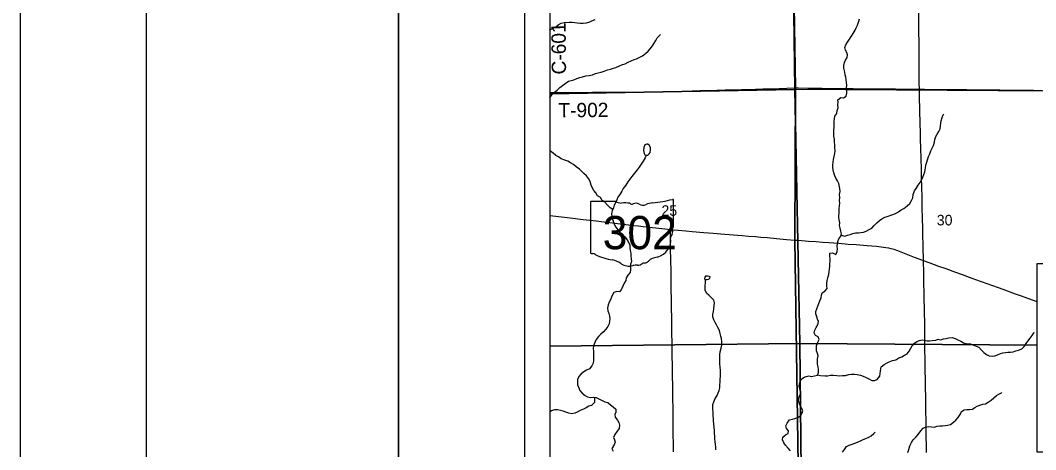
# Model space of a CAD drawing. Extents: x 0 to 34, y 0 to 22.
# Drawn here: x 0 to 4.028, y 17.462 to 19.165 of the extents above; entities that cross this region are included whole.
import ezdxf

# ---------------------------------------------------------------- set-up
doc = ezdxf.new("R2010")
doc.units = 0
for name, color, linetype in [('Default', 7, 'Continuous'), ('GM_X_County_Road_Text', 7, 'Continuous'), ('GM_X_Interstate_Route', 7, 'Continuous'), ('GM_X_Minor_Lake', 7, 'Continuous'), ('GM_X_Minor_River', 7, 'Continuous'), ('GM_X_Section', 7, 'Continuous'), ('GM_X_Section_Text', 7, 'Continuous'), ('GM_X_State_Location', 7, 'Continuous'), ('GM_X_State_Route', 7, 'Continuous'), ('GM_X_State_Shield', 7, 'Continuous'), ('GM_X_Township_Road', 7, 'Continuous'), ('GM_X_Township_Road_Text', 7, 'Continuous'), ('SH_Border', 7, 'Continuous'), ('SH_Cut_Line', 7, 'Continuous'), ('SH_Data', 7, 'Continuous')]:
    doc.layers.add(name, color=color, linetype=linetype)

msp = doc.modelspace()

# ---------------------------------------------------------------- linework, layer by layer
at = {"layer": 'Default'}
for points in [[(2.1, 19.8813), (2.1, 18.8733), (3.073, 18.8909), (3.0592, 19.8987), (3.0228, 19.9046), (2.4888, 19.8857)], [(2.1, 18.8733), (2.1, 17.8727), (3.0924, 17.8824), (3.073, 18.8909)], [(2.1, 17.8727), (2.1, 16.8795), (2.253, 16.8782), (3.1023, 16.8785), (3.0924, 17.8824)]]:
    msp.add_lwpolyline(points, close=True, dxfattribs=at)
at = {"layer": 'GM_X_Interstate_Route'}
msp.add_lwpolyline([(3.0331, 20.9), (2.1, 20.9), (2.1, 16.8784), (2.6014, 16.878), (3.0939, 16.8719), (3.0724, 18.2926), (3.0747, 18.8969), (3.067, 19.3838), (3.0588, 19.9042)], close=True, dxfattribs=at)
msp.add_lwpolyline([(8.1285, 16.8707), (8.1148, 17.8694), (8.0976, 18.2853), (8.0958, 18.3144), (8.0817, 18.88), (8.0959, 19.2713), (8.1023, 19.3817), (8.0929, 19.6339), (8.0678, 20.8562), (8.0675, 20.8733), (8.067, 20.8954), (8.0669, 20.9), (3.0331, 20.9), (3.0588, 19.9042), (3.067, 19.3838), (3.0747, 18.8969), (3.0724, 18.2926), (3.0939, 16.8719)], dxfattribs=at)
at = {"layer": 'GM_X_Minor_Lake'}
for points in [[(2.4888, 18.6297), (2.4941, 18.6349), (2.4983, 18.6402), (2.5003, 18.6516), (2.5004, 18.6588), (2.4955, 18.6676), (2.4899, 18.6737), (2.485, 18.6737), (2.477, 18.6704), (2.4735, 18.6606), (2.4719, 18.6481), (2.4744, 18.637)], [(2.4744, 18.637), (2.4772, 18.6309), (2.4801, 18.6297), (2.4821, 18.6293), (2.4839, 18.6294), (2.4888, 18.6297)], [(2.7247, 18.1372), (2.73, 18.1383), (2.7326, 18.1401), (2.7357, 18.142), (2.7369, 18.1469), (2.7323, 18.1485), (2.7267, 18.1505), (2.7183, 18.1502), (2.7149, 18.146), (2.7137, 18.14), (2.7166, 18.137)], [(2.7166, 18.137), (2.7247, 18.1372)]]:
    msp.add_lwpolyline(points, dxfattribs=at)
at = {"layer": 'GM_X_Minor_River'}
for points in [[(2.1, 19.1258), (2.1011, 19.1266), (2.1114, 19.1322), (2.1232, 19.1374), (2.1342, 19.1468), (2.1452, 19.1531), (2.1574, 19.1564), (2.1771, 19.1577), (2.1892, 19.1572), (2.1998, 19.1556), (2.2096, 19.1548), (2.2214, 19.1535), (2.2327, 19.153), (2.2456, 19.1544), (2.2589, 19.1588), (2.2703, 19.164), (2.2809, 19.1681)], [(3.2243, 18.602), (3.2255, 18.6126), (3.2279, 18.6244), (3.2306, 18.6361), (3.2319, 18.6467), (3.2316, 18.66), (3.2309, 18.671), (3.2303, 18.6809), (3.2296, 18.6934), (3.2271, 18.7059), (3.2275, 18.7162), (3.2276, 18.7298), (3.2285, 18.7397), (3.2278, 18.753), (3.2279, 18.7632), (3.2292, 18.7738), (3.2315, 18.7852), (3.2384, 18.7954), (3.2397, 18.8064), (3.2443, 18.8181), (3.2433, 18.8298), (3.2441, 18.8397), (3.2431, 18.8496), (3.2545, 18.8589), (3.2651, 18.8569), (3.2754, 18.8641), (3.2785, 18.8762), (3.279, 18.8864), (3.2779, 18.8959), (3.2784, 18.9073), (3.277, 18.9187), (3.2759, 18.9289), (3.2749, 18.9388), (3.2716, 18.9491), (3.2701, 18.9597), (3.2672, 18.9745), (3.2666, 18.9859), (3.2689, 18.9969), (3.2732, 19.0067), (3.2805, 19.0173), (3.2817, 19.0275), (3.2787, 19.037), (3.2735, 19.0469), (3.271, 19.0568), (3.2741, 19.067), (3.2814, 19.0783), (3.2967, 19.1017), (3.3044, 19.113), (3.3117, 19.1251), (3.3163, 19.1353), (3.3206, 19.1459), (3.3268, 19.161), (3.3287, 19.1708)], [(2.1, 18.8567), (2.1007, 18.8573), (2.1091, 18.8686), (2.1194, 18.8799), (2.129, 18.8881), (2.14, 18.8983), (2.1503, 18.9065), (2.1606, 18.9128), (2.1747, 18.9229), (2.1853, 18.9266), (2.196, 18.9292), (2.207, 18.9344), (2.2195, 18.9377), (2.2301, 18.9406), (2.2427, 18.9447), (2.2559, 18.9457), (2.2692, 18.9486), (2.2818, 18.9542), (2.2916, 18.956), (2.3045, 18.9596), (2.3159, 18.9633), (2.3288, 18.9681), (2.3417, 18.971), (2.3531, 18.9755), (2.3626, 18.978), (2.3763, 18.9843), (2.3892, 18.9891), (2.3987, 18.9925), (2.4116, 18.9988), (2.4234, 19.0044), (2.4345, 19.0096), (2.4447, 19.0125), (2.4576, 19.0188), (2.4679, 19.024), (2.4797, 19.0334), (2.4904, 19.042), (2.4984, 19.0522), (2.5076, 19.0639), (2.5142, 19.0744), (2.5211, 19.0846), (2.5268, 19.0948), (2.5349, 19.1046), (2.5394, 19.1079)], [(3.256, 18.3129), (3.2706, 18.3091), (3.2817, 18.3131), (3.2915, 18.3157), (3.3029, 18.3194), (3.3132, 18.3215), (3.3245, 18.3222), (3.3344, 18.3236), (3.345, 18.3243), (3.356, 18.3283), (3.3678, 18.3347), (3.3777, 18.3403), (3.3876, 18.3508), (3.3979, 18.3621), (3.4082, 18.3707), (3.4178, 18.3774), (3.4296, 18.3838), (3.4391, 18.3871), (3.4607, 18.3941), (3.4713, 18.3982), (3.4831, 18.4052), (3.4942, 18.4127), (3.5048, 18.4179), (3.5174, 18.4284), (3.5285, 18.4378), (3.5358, 18.4503), (3.5404, 18.4605), (3.5424, 18.4733), (3.5471, 18.4881), (3.5532, 18.4983), (3.562, 18.5107), (3.5697, 18.5216), (3.5759, 18.533), (3.5801, 18.5428), (3.5844, 18.5537), (3.5875, 18.5636), (3.591, 18.5802), (3.5923, 18.5901), (3.5954, 18.6022), (3.6032, 18.6249), (3.6085, 18.6355), (3.6124, 18.6468), (3.6171, 18.6581), (3.6221, 18.6687), (3.626, 18.6816), (3.6283, 18.6918), (3.6322, 18.7035), (3.6376, 18.7133), (3.6434, 18.7235), (3.6488, 18.7341), (3.6496, 18.7466), (3.6512, 18.7564), (3.6532, 18.7663), (3.6567, 18.7788), (3.6614, 18.7901), (3.6633, 18.7927)], [(2.3501, 18.4146), (2.3405, 18.4217), (2.3288, 18.4317), (2.3183, 18.4435), (2.3085, 18.4505), (2.301, 18.4619), (2.2901, 18.4692), (2.2826, 18.4799), (2.2755, 18.4895), (2.2692, 18.4994), (2.2647, 18.5116), (2.2607, 18.5253), (2.254, 18.5379), (2.2457, 18.5482), (2.2356, 18.5566), (2.2176, 18.5739), (2.2051, 18.5843), (2.195, 18.5923), (2.1829, 18.5996), (2.1713, 18.6058), (2.1595, 18.6097), (2.146, 18.6159), (2.1354, 18.6236), (2.1241, 18.6291), (2.1132, 18.6383), (2.1034, 18.6456), (2.1, 18.6481)], [(2.4827, 18.6294), (2.4785, 18.6195), (2.4704, 18.6063), (2.4631, 18.5943), (2.4554, 18.5826), (2.4474, 18.5717), (2.4367, 18.5581), (2.4263, 18.5453), (2.4175, 18.5348), (2.4103, 18.5246), (2.4018, 18.5106), (2.3911, 18.4971), (2.3857, 18.4873), (2.3784, 18.4744), (2.3707, 18.4635), (2.3657, 18.4533), (2.3618, 18.4431), (2.3553, 18.4318), (2.3526, 18.4204), (2.3475, 18.4087), (2.3456, 18.3985), (2.347, 18.386), (2.3495, 18.3757), (2.3525, 18.3647), (2.3573, 18.3536), (2.3621, 18.3441), (2.3708, 18.3338), (2.3783, 18.3242), (2.388, 18.3177), (2.3985, 18.3054), (2.4075, 18.2947), (2.4128, 18.2844), (2.4176, 18.273), (2.4179, 18.2624), (2.4189, 18.2521), (2.4222, 18.2418), (2.4218, 18.2289), (2.4232, 18.2183), (2.4239, 18.2088), (2.4207, 18.1978), (2.4206, 18.1861), (2.4209, 18.1758), (2.4197, 18.1648), (2.4098, 18.1543), (2.4029, 18.1441), (2.402, 18.1335), (2.3959, 18.1229), (2.3901, 18.1109), (2.385, 18.0984), (2.3774, 18.0882), (2.3657, 18.0887), (2.3546, 18.085), (2.3469, 18.0703), (2.3415, 18.0567), (2.3354, 18.0469), (2.3315, 18.0363), (2.3287, 18.0234), (2.3302, 18.0124), (2.3343, 18.0025), (2.3368, 17.9915), (2.3379, 17.982), (2.3374, 17.9717), (2.3362, 17.9604), (2.3312, 17.9502), (2.3224, 17.94), (2.3136, 17.9291), (2.3025, 17.9205), (2.2933, 17.9107), (2.2842, 17.899), (2.2784, 17.8873), (2.2741, 17.8741), (2.2729, 17.8635), (2.2735, 17.8521), (2.2742, 17.8399), (2.2737, 17.8263), (2.2736, 17.8153), (2.272, 17.805), (2.2674, 17.7945), (2.2574, 17.7832), (2.246, 17.7772), (2.235, 17.7712), (2.2243, 17.763), (2.2151, 17.7525), (2.2105, 17.7396), (2.2108, 17.7294), (2.2107, 17.7191), (2.2155, 17.7073), (2.2192, 17.697), (2.229, 17.6863), (2.2406, 17.6767), (2.2504, 17.6713), (2.2618, 17.6693), (2.2727, 17.6699), (2.2848, 17.6683), (2.2954, 17.6633), (2.3075, 17.6567), (2.3188, 17.6517), (2.3301, 17.6485), (2.341, 17.6401), (2.3516, 17.6324), (2.3617, 17.622)], [(3.0721, 17.5855), (3.0839, 17.59), (3.0957, 17.5978), (3.1015, 17.6076), (3.1038, 17.6175), (3.0982, 17.6281), (3.0927, 17.6392), (3.0886, 17.6499), (3.0864, 17.6609), (3.0895, 17.6734), (3.0949, 17.6836), (3.0946, 17.6938), (3.0921, 17.7033), (3.0895, 17.7147), (3.0919, 17.7284), (3.0977, 17.7405), (3.1072, 17.748), (3.1179, 17.7528), (3.1277, 17.755), (3.1383, 17.7522), (3.1508, 17.7544), (3.1618, 17.7581), (3.1668, 17.7682), (3.1662, 17.7793), (3.1644, 17.7899), (3.1622, 17.8009), (3.1627, 17.8119), (3.1624, 17.8226), (3.1655, 17.8335), (3.1618, 17.8438), (3.1589, 17.8541), (3.1578, 17.864), (3.1579, 17.8738), (3.1637, 17.8886), (3.1691, 17.8991), (3.165, 17.9094), (3.1537, 17.9141), (3.1489, 17.9248), (3.1512, 17.9361), (3.1566, 17.9471), (3.1631, 17.9576), (3.1663, 17.9697), (3.1626, 17.9793), (3.16, 17.9891), (3.1563, 18.0002), (3.1556, 18.0097), (3.1591, 18.0199), (3.1634, 18.0312), (3.1676, 18.0418), (3.1711, 18.0528), (3.1762, 18.0641), (3.1778, 18.0747), (3.1805, 18.0846), (3.1912, 18.0905), (3.2003, 18.1011), (3.1997, 18.1113), (3.1994, 18.1208), (3.2002, 18.1326), (3.203, 18.1432), (3.2076, 18.1564), (3.2092, 18.1689), (3.2101, 18.1787), (3.2113, 18.1882), (3.2114, 18.1988), (3.213, 18.2091), (3.2127, 18.2193), (3.2113, 18.2296), (3.2117, 18.2413), (3.2216, 18.242), (3.2352, 18.2366), (3.2406, 18.2479), (3.2418, 18.2585), (3.2408, 18.2684), (3.242, 18.2778), (3.2424, 18.2873), (3.2467, 18.2987), (3.2547, 18.3085), (3.2575, 18.3183), (3.2553, 18.3282), (3.2523, 18.34), (3.2502, 18.3514), (3.251, 18.362), (3.2488, 18.3738), (3.2467, 18.3837), (3.2476, 18.4057), (3.2481, 18.4189), (3.2509, 18.4394), (3.2499, 18.4496), (3.2503, 18.461), (3.2501, 18.4739), (3.2517, 18.4864), (3.2507, 18.4978), (3.2463, 18.5176), (3.2411, 18.5275), (3.2351, 18.5382), (3.2314, 18.5485), (3.227, 18.5595), (3.224, 18.5717), (3.2234, 18.5812), (3.2234, 18.5922), (3.2243, 18.602)], [(2.7469, 17.9886), (2.747, 17.9981), (2.7501, 18.0102), (2.7517, 18.0204), (2.7526, 18.033), (2.7534, 18.0443), (2.7508, 18.055), (2.7418, 18.0646), (2.7317, 18.0741), (2.7216, 18.0833), (2.7171, 18.094), (2.7172, 18.1043), (2.7169, 18.1137), (2.7177, 18.124), (2.7175, 18.1357), (2.7175, 18.137)], [(2.7594, 17.4615), (2.7592, 17.4725), (2.7577, 17.4827), (2.7567, 17.4941), (2.7556, 17.5047), (2.7554, 17.5146), (2.7543, 17.5279), (2.7537, 17.5378), (2.7522, 17.5499), (2.7505, 17.5647), (2.7498, 17.5761), (2.7495, 17.5856), (2.7485, 17.5959), (2.7482, 17.6054), (2.7469, 17.6289), (2.7477, 17.6407), (2.7505, 17.6516), (2.7562, 17.6645), (2.7639, 17.6766), (2.7686, 17.6871), (2.7728, 17.697), (2.7744, 17.7076), (2.7753, 17.7189), (2.7765, 17.7292), (2.7766, 17.7402), (2.7771, 17.7538), (2.7773, 17.7774), (2.7758, 17.788), (2.7745, 17.8036), (2.7746, 17.8161), (2.7743, 17.8256), (2.7751, 17.8377), (2.7768, 17.8502), (2.7795, 17.8642), (2.7827, 17.8767), (2.7824, 17.8896), (2.781, 17.9022), (2.7784, 17.9124), (2.7762, 17.9227), (2.7729, 17.9345), (2.7666, 17.9471), (2.7614, 17.9574), (2.7565, 17.9669), (2.7509, 17.9772), (2.7469, 17.9886)], [(3.1625, 17.7593), (3.1739, 17.7557), (3.1921, 17.7543), (3.2023, 17.7554), (3.2133, 17.7576), (3.2258, 17.7574), (3.2391, 17.7562), (3.2508, 17.7553), (3.2614, 17.7559), (3.2739, 17.7566), (3.2872, 17.7602), (3.2974, 17.762), (3.3095, 17.7615), (3.3198, 17.7607), (3.3326, 17.7579), (3.3439, 17.754), (3.3556, 17.7482), (3.3681, 17.7412), (3.3782, 17.7362), (3.3885, 17.7369), (3.3991, 17.7409), (3.4098, 17.7541), (3.4114, 17.7647), (3.4123, 17.775), (3.4151, 17.7909), (3.4261, 17.7999), (3.4356, 17.8055), (3.4463, 17.8103), (3.4603, 17.8155), (3.4728, 17.8188), (3.4846, 17.8259), (3.4964, 17.8303), (3.5078, 17.8374), (3.5177, 17.8422), (3.5265, 17.852), (3.5331, 17.8641), (3.5384, 17.8739), (3.5469, 17.8848), (3.5564, 17.8908), (3.5666, 17.8953), (3.5773, 17.897), (3.5871, 17.8962), (3.5969, 17.8931), (3.6071, 17.893), (3.6178, 17.8944), (3.6314, 17.8969), (3.6409, 17.8998), (3.6519, 17.8975), (3.6625, 17.9012), (3.6731, 17.9026), (3.6834, 17.9051), (3.6962, 17.9065), (3.7087, 17.9026), (3.7189, 17.8976), (3.7313, 17.8921), (3.7419, 17.8863), (3.7544, 17.882), (3.7687, 17.8811), (3.7786, 17.8776), (3.7914, 17.873), (3.8027, 17.8679), (3.8132, 17.8564), (3.8222, 17.8469), (3.8324, 17.8395), (3.8429, 17.8345), (3.8554, 17.8329), (3.866, 17.8343), (3.8767, 17.838), (3.8881, 17.8428), (3.8976, 17.8457), (3.9082, 17.8475), (3.9177, 17.8486), (3.9279, 17.8489), (3.9381, 17.8503), (3.9491, 17.8536), (3.9598, 17.8569), (3.9723, 17.8613), (3.9818, 17.8715), (3.9899, 17.8824), (3.9968, 17.8926), (4.0056, 17.9043), (4.0136, 17.9148), (4.0209, 17.925), (4.0225, 17.9261)], [(3.5208, 17.4514), (3.524, 17.4631), (3.5286, 17.4771), (3.5348, 17.4907), (3.5413, 17.5013), (3.5517, 17.5122), (3.562, 17.5223), (3.5716, 17.5363), (3.5811, 17.5475), (3.5906, 17.5513), (3.6028, 17.5538), (3.6149, 17.5525), (3.6255, 17.5513), (3.6376, 17.555), (3.6482, 17.5568), (3.6581, 17.5559), (3.6691, 17.5581), (3.6785, 17.5595), (3.6903, 17.562), (3.7017, 17.571), (3.7113, 17.5789), (3.7204, 17.5898), (3.7277, 17.6015), (3.7339, 17.614), (3.7442, 17.6203), (3.7548, 17.6214), (3.7658, 17.6209), (3.7768, 17.6223), (3.7863, 17.6298), (3.7958, 17.6342), (3.8064, 17.6383), (3.8178, 17.642), (3.8281, 17.6442), (3.8395, 17.6505), (3.8509, 17.6588), (3.8623, 17.6674), (3.8719, 17.6764), (3.8818, 17.6827), (3.8921, 17.6872), (3.8936, 17.6894)], [(2.2778, 17.6693), (2.2776, 17.6593), (2.2775, 17.6487), (2.2653, 17.6366), (2.2554, 17.6344), (2.2451, 17.6277), (2.2337, 17.6221), (2.2212, 17.6177), (2.2094, 17.6102), (2.1999, 17.6069), (2.1881, 17.6047), (2.1757, 17.6071), (2.1636, 17.6103), (2.153, 17.6142), (2.1428, 17.6173), (2.1315, 17.6197), (2.119, 17.6198), (2.1068, 17.6158), (2.1, 17.6122)], [(2.3617, 17.622), (2.3627, 17.611), (2.3581, 17.6008), (2.3603, 17.5906), (2.3689, 17.5795), (2.3745, 17.5699), (2.3774, 17.5585), (2.3754, 17.546), (2.3674, 17.5351), (2.3578, 17.5219), (2.3532, 17.5109), (2.3573, 17.501), (2.3602, 17.4911), (2.3563, 17.4813), (2.3471, 17.4666), (2.3512, 17.4559)], [(3.0555, 17.4578), (3.0461, 17.4681), (3.0349, 17.4793), (3.0285, 17.4896), (3.0237, 17.5014), (3.0253, 17.5116), (3.036, 17.5206), (3.0455, 17.5258), (3.0471, 17.5361), (3.0392, 17.5464), (3.0363, 17.557), (3.0421, 17.5672), (3.0516, 17.5804), (3.0626, 17.583), (3.0721, 17.5855)], [(3.2618, 17.4516), (3.2699, 17.4629), (3.2772, 17.4739), (3.2878, 17.4802), (3.3, 17.4843), (3.311, 17.4883), (3.3216, 17.492), (3.3323, 17.4969), (3.3441, 17.5017), (3.3539, 17.5057), (3.3654, 17.5117), (3.3752, 17.5173), (3.3863, 17.5259), (3.3905, 17.5312)]]:
    msp.add_lwpolyline(points, dxfattribs=at)
at = {"layer": 'GM_X_Section'}
for points in [[(4.0799, 19.8852), (4.08, 18.8834), (3.073, 18.8909), (3.0592, 19.8987), (3.0869, 19.8862)], [(4.0919, 18.2003), (4.08, 18.8834), (3.073, 18.8909), (3.0924, 17.8824), (4.0336, 17.8765), (4.0336, 18.2003)], [(4.0336, 17.8765), (3.0924, 17.8824), (3.1023, 16.8785), (3.2153, 16.8759), (4.1045, 16.8706), (4.1005, 17.4527), (4.0336, 17.4527)]]:
    msp.add_lwpolyline(points, close=True, dxfattribs=at)
at = {"layer": 'GM_X_State_Route'}
for points in [[(3.5945, 17.4514), (3.5936, 17.5389), (3.593, 17.5722), (3.5919, 17.6203), (3.5914, 17.6651), (3.5906, 17.7132), (3.5903, 17.7438), (3.5899, 17.7716), (3.5894, 17.7983), (3.5891, 17.8198), (3.5886, 17.8591), (3.5884, 17.9029), (3.5876, 17.9552), (3.5861, 18.0154), (3.5851, 18.0674), (3.5845, 18.1381), (3.5838, 18.1704), (3.5832, 18.2036), (3.583, 18.211), (3.5815, 18.268), (3.5805, 18.318), (3.5796, 18.346), (3.5792, 18.374), (3.5779, 18.4289), (3.5773, 18.469), (3.5766, 18.4983), (3.5753, 18.547), (3.575, 18.5759), (3.5733, 18.6154), (3.5724, 18.6581), (3.5714, 18.6933), (3.5704, 18.7213), (3.5694, 18.7539), (3.5671, 18.8621), (3.5666, 18.8917), (3.5661, 18.9173), (3.5661, 18.9548), (3.5662, 19.0002), (3.5658, 19.0621), (3.5645, 19.1347), (3.5646, 19.2652)], [(3.0726, 18.2921), (3.0399, 18.2947), (2.9997, 18.2983), (2.9625, 18.3015), (2.9378, 18.3036), (2.9161, 18.3056), (2.8882, 18.3076), (2.8635, 18.3095), (2.8294, 18.3123), (2.7953, 18.3153), (2.7489, 18.3192), (2.7117, 18.3225), (2.6653, 18.3265), (2.6405, 18.3285), (2.6096, 18.3312), (2.591, 18.3329), (2.5802, 18.334), (2.5324, 18.339), (2.4955, 18.3435), (2.4708, 18.3463), (2.4523, 18.3482), (2.4338, 18.3503), (2.4122, 18.3526), (2.369, 18.3577), (2.3382, 18.3615), (2.3042, 18.3657), (2.2857, 18.3678), (2.2333, 18.3738), (2.1809, 18.3804), (2.113, 18.3883), (2.1, 18.3899)], [(4.0336, 18.0477), (4.0003, 18.0599), (3.9712, 18.0708), (3.9478, 18.0792), (3.8982, 18.0973), (3.8806, 18.1035), (3.8572, 18.1119), (3.8134, 18.1276), (3.7899, 18.1359), (3.7753, 18.1411), (3.7374, 18.1551), (3.7112, 18.1648), (3.6732, 18.1785), (3.6439, 18.1888), (3.6089, 18.2017), (3.583, 18.211), (3.5796, 18.2122), (3.5477, 18.2241), (3.5072, 18.2401), (3.4811, 18.2501), (3.4664, 18.2552), (3.4544, 18.2586), (3.4452, 18.2606), (3.433, 18.2629), (3.4145, 18.2655), (3.3959, 18.2675), (3.3588, 18.2704), (3.3155, 18.2737), (3.2845, 18.2763), (3.2473, 18.2791), (3.2256, 18.2807), (3.2071, 18.2821), (3.1823, 18.2839), (3.1576, 18.2858), (3.1266, 18.2881), (3.0863, 18.291), (3.0726, 18.2921)]]:
    msp.add_lwpolyline(points, dxfattribs=at)
at = {"layer": 'GM_X_State_Shield'}
for p, q in [((2.5908, 18.3466), (2.5908, 18.4513)), ((2.2612, 18.4429), (2.2612, 18.2428)), ((2.361, 18.4464), (2.2644, 18.4464)), ((2.5908, 18.3467), (2.5908, 18.3466))]:
    msp.add_line(p, q, dxfattribs=at)
for centre, major_axis, start_param, end_param in [((2.4734, 18.7192), (0.3495, 0), 4.814394, 5.042369), ((2.5871, 18.4518), (0.00367, 0), 6.141152, 7.989035), ((2.265, 18.4434), (0.00382, 0), 1.712693, 3.28349), ((2.384, 18.4696), (0.037, 0), 4.042523, 4.731795), ((2.3962, 18.334), (0.133, 0), 1.404758, 1.657858), ((2.4264, 18.4444), (0.0107, 0), 3.836095, 5.185415), ((2.4421, 18.4213), (0.0222, 0), 0.950623, 2.079405), ((2.4708, 18.453), (0.0267, 0), 4.081561, 5.145723), ((2.518, 18.3853), (0.0703, 0), 1.699011, 2.107814), ((2.5899, 18.339), (0.00568, 0), 1.883978, 3.671073), ((2.5538, 18.3257), (0.0341, 0), 5.934695, 6.695948), ((2.5869, 18.3462), (0.00393, 0), 5.05454, 6.418171), ((2.493, 18.2895), (0.0874, 0), 5.101752, 6.440018), ((2.6039, 18.3028), (0.0248, 0), 2.387724, 3.262537), ((2.265, 18.2424), (0.00385, 0), 3.00124, 4.508301), ((2.2656, 18.2628), (0.0294, 0), 4.665946, 4.897461), ((2.2716, 18.2313), (0.0106, 0), 0.519207, 1.627899), ((2.4054, 18.4111), (0.2524, 0), 4.195997, 4.488961), ((2.3302, 18.1529), (0.079, 0), 0.823519, 1.323587), ((2.4692, 18.2234), (0.0282, 0), 4.937069, 5.64225), ((2.5298, 18.1866), (0.0479, 0), 1.647645, 2.488434), ((2.4156, 18.2303), (0.0501, 0), 4.026481, 4.996735), ((2.4446, 18.1611), (0.0412, 0), 1.495662, 1.94098), ((2.4482, 18.2153), (0.0267, 0), 4.691044, 5.507374), ((2.4724, 18.1959), (0.00752, 0), 1.147584, 2.315152)]:
    msp.add_ellipse(centre, major_axis=major_axis, ratio=0.8, start_param=start_param, end_param=end_param, dxfattribs=at)
at = {"layer": 'GM_X_Township_Road'}
for points in [[(2.1, 18.878), (2.1118, 18.878), (2.1366, 18.8782), (2.1926, 18.8785), (2.2268, 18.8787), (2.2704, 18.8793), (2.3139, 18.8794), (2.3637, 18.8799), (2.4228, 18.8801), (2.4663, 18.8804), (2.4881, 18.8805), (2.516, 18.8811), (2.5502, 18.8817), (2.5751, 18.8818), (2.6, 18.8823), (2.6404, 18.8838), (2.6652, 18.8848), (2.6963, 18.8858), (2.7305, 18.8869), (2.7958, 18.8889), (2.8611, 18.8904), (2.917, 18.8919), (2.945, 18.8926), (3.0102, 18.8946), (3.0413, 18.8954), (3.075, 18.8964)], [(3.075, 18.8964), (3.0871, 18.8963), (3.1243, 18.8957), (3.1585, 18.8954), (3.1801, 18.8952), (3.2049, 18.8949), (3.2236, 18.8947), (3.264, 18.8944), (3.2889, 18.8944), (3.3044, 18.8942), (3.3509, 18.8935), (3.382, 18.8932), (3.4379, 18.8926), (3.4721, 18.8924), (3.5094, 18.892), (3.5404, 18.8917), (3.5622, 18.8918), (3.5666, 18.8917)], [(3.5666, 18.8917), (3.587, 18.8912), (3.6337, 18.8908), (3.6679, 18.8904), (3.7114, 18.8899), (3.7549, 18.8897), (3.8077, 18.8892), (3.8482, 18.8888), (3.8854, 18.8884), (3.932, 18.888), (3.9507, 18.8877), (3.9911, 18.8873), (4.0189, 18.8871), (4.0531, 18.8866)], [(2.5909, 17.454), (2.5899, 17.5535), (2.5892, 17.625), (2.5887, 17.6655), (2.5885, 17.6841), (2.5881, 17.7059), (2.5879, 17.7245), (2.5875, 17.7463), (2.5867, 17.8022), (2.5863, 17.8271), (2.5859, 17.855), (2.5856, 17.8769), (2.5854, 17.8927), (2.5851, 17.9172), (2.5842, 17.9669), (2.5819, 18.1162), (2.5812, 18.169), (2.5798, 18.2592), (2.5796, 18.2997), (2.5797, 18.3214), (2.5799, 18.3277), (2.5802, 18.334)]]:
    msp.add_lwpolyline(points, dxfattribs=at)
at = {"layer": 'SH_Border'}
for points in [[(0.5, 21.5), (1.5, 21.5), (1.5, 0.5), (0.5, 0.5)], [(1.5, 21.5), (33.5, 21.5), (33.5, 0.5), (1.5, 0.5)]]:
    msp.add_lwpolyline(points, close=True, dxfattribs=at)
at = {"layer": 'SH_Cut_Line'}
msp.add_lwpolyline([(0, 0), (34, 0), (34, 22), (0, 22)], close=True, dxfattribs=at)
msp.add_lwpolyline([(8.1285, 16.8707), (8.1148, 17.8694), (8.0976, 18.2853), (8.0958, 18.3144), (8.0817, 18.88), (8.0959, 19.2713), (8.1023, 19.3817), (8.0929, 19.6339), (8.0678, 20.8562), (8.0675, 20.8733), (8.067, 20.8954), (8.0669, 20.9), (2.1, 20.9), (2.1, 14.1)], dxfattribs=at)
at = {"layer": 'SH_Data'}
for p, q in [((2, 21), (2, 14)), ((2.1, 20.9), (2.1, 14.1))]:
    msp.add_line(p, q, dxfattribs=at)

# ---------------------------------------------------------------- texts
at = {"layer": 'GM_X_County_Road_Text'}
msp.add_text('C-601', height=0.05682, rotation=90.5516, dxfattribs=at).set_placement((2.165, 18.95))
at = {"layer": 'GM_X_Section_Text'}
for s, p in [('25', (2.5433, 18.3893)), ('30', (3.6354, 18.3514))]:
    msp.add_text(s, height=0.04186, rotation=0, dxfattribs=at).set_placement(p)
at = {"layer": 'GM_X_State_Location'}
for s in ['s', 'r']:
    msp.add_text(s, height=0.000189, dxfattribs=at).set_placement((2.4223, 18.3296))
msp.add_text('302', height=0.000189, rotation=0, dxfattribs=at).set_placement((2.3554, 18.3158))
at = {"layer": 'GM_X_State_Shield'}
msp.add_text('302', height=0.13184, dxfattribs=at).set_placement((2.3102, 18.2569))
at = {"layer": 'GM_X_Township_Road_Text'}
msp.add_text('T-902', height=0.05682, rotation=0.5592, dxfattribs=at).set_placement((2.1347, 18.7794))

doc.saveas('drawing.dxf')
